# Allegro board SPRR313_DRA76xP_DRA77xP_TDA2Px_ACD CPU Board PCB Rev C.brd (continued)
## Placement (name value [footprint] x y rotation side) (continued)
TP82  TP  [TP-30RD13]  123.44 46.35 0 top
TP83  SMT-TP  [TP1-70X135]  4.7 14.99 0 top
TP84  SMT-TP  [TP1-70X135]  197.74 14.1 0 top
TP85  TP  [TP1-6040]  190.75 37.47 0 top
TP86  SMT-TP  [TP1-70X135]  212.98 165.23 180 bottom
TP87  SMT-TP  [TP1-70X135]  8.89 175.13 180 bottom
TP88  TP  [TP1-18RD8]  128.52 83.69 0 top
TP89  TP  [TP20]  44.96 50.04 270 bottom
TP90  TP  [TP-30RD13]  142.49 32.13 0 top
TP91  TP  [TP1-6040]  19 87.04 180 bottom
TP92  SMT-TP  [TP1-70X135]  4.95 15.11 90 bottom
TP93  SMT-TP  [TP1-70X135]  197.74 14.48 180 bottom
TP94  TP  [TP-30RD13]  47.75 128.78 0 top
TP95  TP  [TP-30RD13]  47.75 130.18 0 top
TP96  TP  [TP-30RD13]  211.46 123.95 0 top
TP97  TP  [TP1-18RD8]  64.01 74.04 0 top
TP98  TP  [TP-30RD13]  205.23 123.95 0 top
TP99  SMT-TP  [TP1-70X135]  107.06 123.32 0 top
TP100  SMT-TP  [TP1-70X135]  101.22 85.6 180 bottom
U1  TPS2065D  [SO8-25X75]  18.67 174.24 180 top
U2  TPS2065D  [SO8-25X75]  29.84 162.81 270 top
U3  FT232RQ  [QFN32_5X5]  167.51 164.59 90 top
U4  74LV1G126CRG4  [DCK-5]  55.12 163.7 90 top
U5  TPS3808G09DBVRG4  [DBV6-27X39-6]  60.45 161.29 270 top
U6  TPS3808G09DBVRG4  [DBV6-27X39-6]  60.45 157.48 270 top
U7  74LVC1G08DCK  [DCK-5]  55.12 157.35 90 top
U8  DS90UB921-Q1  [RHS48-11X34]  152.15 155.32 90 top
U9  LM74610  [DGK8-14X70]  177.8 154.05 180 top
U10  CDCM9102RHBR  [QFN32_202SQ]  25.15 149.1 90 top
U11  CDCE813QPWRQ1  [PW14-12X70]  159.38 146.3 0 top
U12  MT29F4G16ABADAWP:D  [TSOP48-10X60-MICRON]  131.95 143.51 270 top
U13  tps1h100-q1  [PWP14-14X70-PAD]  8.89 140.72 270 top
U14  tps1h100-q1  [PWP14-14X70-PAD]  211.84 147.19 180 top
U15  MTFC8GLWDM-3M AIT Z  [FBGA153-169-P5-COMBO]  150.5 132.21 0 top
U16  74LVC1G08DCK  [DCK-5]  210.69 129.03 0 top
U17  SN74LVC1G04DCK  [DCK-5]  129.16 114.81 0 top
U18  TPS43351QDAPRQ1  [DAP38]  175.26 113.03 270 top
U19  TPD12S016RKTR  [RKT24]  13.97 111.76 0 top
U20  S25FL256SAGMFV001  [SO16-25X75-300]  108.71 110.24 90 top
U21  PCF8575  [PW24-14X70]  200.41 77.98 270 top
U22  tpd1e05u06  [DPY-RDPADS]  14.1 106.68 135 top
U23  SN74LVC1G04DCK  [DCK-5]  68.83 105.03 0 top
U24  tpd1e05u06  [DPY-RDPADS]  14.1 104.9 225 top
U25  tpd1e05u06  [DPY-RDPADS]  16 103.63 135 top
U26  tpd1e05u06  [DPY-RDPADS]  16 101.85 225 top
U27  SN74LVC1G04DCK  [DCK-5]  119.63 101.6 0 top
U28  tpd1e05u06  [DPY-RDPADS]  16 99.57 135 top
U29  tpd1e05u06  [DPY-RDPADS]  16 97.79 225 top
U30  PCF8575  [PW24-14X70]  200.66 66.42 270 top
U31  tpd1e05u06  [DPY-RDPADS]  14.1 96.52 135 top
U32  tpd1e05u06  [DPY-RDPADS]  14.1 94.74 225 top
U33  tpd1e05u06  [DPY-RDPADS]  11.81 80.64 135 top
U34  tpd1e05u06  [DPY-RDPADS]  11.81 79.12 225 top
U35  tpd1e05u06  [DPY-RDPADS]  11.81 77.47 135 top
U36  tpd1e05u06  [DPY-RDPADS]  11.81 75.95 225 top
U37  TPS73101DBVR  [DBV5-27X39]  121.92 42.04 0 top
U38  O917A14ATRGZRQ1  [RGZ48-11X34]  163.7 69.98 90 top
U39  SN74AVC8T245RHL  [RHL24-PVQFN-TI]  17.02 67.56 90 top
U40  LP87565CRNFRQ1  [VQFNHR26]  137.54 60.07 0 top
U41  SN74AVC4T245RGYR  [RGY16-12X34]  17.02 59.56 90 top
U42  X577PXGACD  [SKTBGA-ZKK-6334-P784]  92.58 56.36 270 top
U43  SN74AVC8T245RHL  [RHL24-PVQFN-TI]  17.02 51.94 90 top
U44  SN74LVC1G04DCK  [DCK-5]  157.86 57.28 270 top
U45  TPS77018DBVT  [DBV5-27X39]  184.78 48.9 180 top
U46  74LVC1G08DCK  [DCK-5]  196.22 44.96 0 top
U47  74LVC1G08DCK  [DCK-5]  199.39 44.96 0 top
U48  74LVC1G08DCK  [DCK-5]  203.84 44.96 0 top
U50  TLV320AIC3106  [RGZ48-11X34]  175.13 43.31 270 top
U51  74LV1G126CRG4  [DCK-5]  116.2 41.78 270 top
U52  TPD4E002  [DRL5-12X40]  214.12 41.15 180 top
U53  TMP102AIDRLT  [DRL6-12X30]  110.13 40.77 180 top
U54  74LV1G126CRG4  [DCK-5]  116.2 38.86 270 top
U55  PCA9306/PCA9306-Q1  [DCU8-10X50]  17.14 37.08 180 top
U56  TPS74801  [DRC10-11X33]  3.43 28.07 0 top
U57  TCAN1042HGVQ1  [SO8-25X75]  199.77 30.73 270 top
U58  TCAN1042HGVQ1  [SO8-25X75]  213.74 25.02 180 top
U59  MT41K512M16HA-125 AIT:A (IT)  [BGA6X16-P8-RE-PKG]  64.77 23.98 0 top
U60  MT41K512M16HA-125 AIT:A (IT)  [BGA6X16-P8-RE-PKG]  77.47 23.98 0 top
U61  MT41K512M8RH-125-AAT:E  (IT)  [INTBGA6X13-P8-RA-PKG]  113.92 23.37 0 top
U62  MT41K512M8RH-125-AAT:E  (IT)  [INTBGA6X13-P8-RA-PKG]  128.27 23.37 0 top
U63  MT41K512M8RH-125-AAT:E (IT)  [BGA6X13-P8-RA-PKG]  90.17 22.78 0 top
U65  INA226AIDGSR  [DGS10-11X60]  154.43 86.11 0 bottom
U66  INA226AIDGSR  [DGS10-11X60]  159.13 86.11 0 bottom
U67  INA226AIDGSR  [DGS10-11X60]  178.56 61.85 270 bottom
U68  INA226AIDGSR  [DGS10-11X60]  179.83 65.53 270 bottom
U69  INA226AIDGSR  [DGS10-11X60]  179.83 69.22 270 bottom
U70  INA226AIDGSR  [DGS10-11X60]  162.69 58.04 0 bottom
U71  INA226AIDGSR  [DGS10-11X60]  179.83 54.48 90 bottom
U72  INA226AIDGSR  [DGS10-11X60]  172.97 57.78 180 bottom
U73  INA226AIDGSR  [DGS10-11X60]  179.83 58.17 270 bottom
U74  INA226AIDGSR  [DGS10-11X60]  172.34 83.95 0 bottom
U75  INA226AIDGSR  [DGS10-11X60]  182.88 77.09 270 bottom
U76  INA226AIDGSR  [DGS10-11X60]  150.37 59.18 90 bottom
U77  INA226AIDGSR  [DGS10-11X60]  146.94 63.25 270 bottom
U78  INA226AIDGSR  [DGS10-11X60]  146.94 55.24 270 bottom
U79  INA226AIDGSR  [DGS10-11X60]  130.3 40.64 270 top
U80  INA226AIDGSR  [DGS10-11X60]  141.22 14.22 270 top
U81  INA226AIDGSR  [DGS10-11X60]  145.8 92.33 0 top
U82  INA226AIDGSR  [DGS10-11X60]  163.83 86.23 0 bottom
U83  INA226AIDGSR  [DGS10-11X60]  176.91 84.07 0 bottom
U84  INA226AIDGSR  [DGS10-11X60]  146.94 67.18 90 bottom
U85  INA226AIDGSR  [DGS10-11X60]  137.54 73.41 0 bottom
U86  INA226AIDGSR  [DGS10-11X60]  137.54 46.86 180 bottom
U87  INA226AIDGSR  [DGS10-11X60]  150.37 92.33 0 top
U88  INA226AIDGSR  [DGS10-11X60]  166.62 98.3 270 bottom
U89  INA226AIDGSR  [DGS10-11X60]  179.96 93.85 90 bottom
U90  INA226AIDGSR  [DGS10-11X60]  187.07 145.8 0 bottom
U91  INA226AIDGSR  [DGS10-11X60]  182.88 73.28 270 bottom
U92  TPD4S014DSQ  [DSQ10-SON]  73.53 174.24 0 bottom
U93  TPS74801  [DRC10-11X33]  82.8 164.08 0 bottom
U94  SN74LVC1G04DCK  [DCK-5]  48.13 163.32 0 bottom
U95  SN74LVC1G04DCK  [DCK-5]  43.05 163.32 0 bottom
U96  TPS22965DSG  [DSG8-11X20]  121.41 157.1 180 bottom
U97  TPD2E001DRL-Q1  [DRL5-12X40]  139.06 156.72 0 bottom
U98  TPD2E001DRL-Q1  [DRL5-12X40]  134.49 156.72 0 bottom
U99  TPD2E001DRL-Q1  [DRL5-12X40]  129.92 156.72 0 bottom
U100  TPD2E001DRL-Q1  [DRL5-12X40]  126.11 156.72 0 bottom
U101  DP83867IRPAP  [PAP64-12X70]  91.95 151.64 0 bottom
U102  TPS74801  [DRC10-11X33]  77.98 149.48 0 bottom
U103  74LVC1G08DCK  [DCK-5]  82.55 143.89 270 bottom
U104  S29GL512S10TFI010  [TSOP56-12X75]  131.95 143.51 90 bottom
U105  SN74LVC1G125DCKR  [DCK-5]  64.77 143.51 180 bottom
U106  74LVC1G08DCK  [DCK-5]  82.55 141.1 270 bottom
U107  74LVC1G08DCK  [DCK-5]  82.55 138.05 270 bottom
U108  DP83867IRPAP  [PAP64-12X70]  98.3 131.32 0 bottom
U109  SN74LVC1G125DCKR  [DCK-5]  142.24 128.78 0 bottom
U110  PCF8575  [PW24-14X70]  73.28 128.02 270 bottom
U111  SN74LVC1G125DCKR  [DCK-5]  62.61 127.13 90 bottom
U112  SN74LVC1G125DCKR  [DCK-5]  62.48 131.57 90 bottom
U113  SN74LVC2G74DCT  [DCT8-14X70]  216.15 133.35 0 bottom
U114  TPS3808G33DBVRG4  [DBV6-27X39-6]  210.57 133.48 0 bottom
U115  DS90Ux949AQ  [RGC64-11X28]  27.94 122.94 90 bottom
U116  SN74LVC1G04DCK  [DCK-5]  146.94 117.47 270 bottom
U117  TPS74801  [DRC10-11X33]  30.99 102.36 180 bottom
U118  SN74LVC1G04DCK  [DCK-5]  79.12 105.16 90 bottom
U119  TPS22965DSG  [DSG8-11X20]  147.83 99.82 0 bottom
U120  TPD4S014DSQ  [DSQ10-SON]  5.71 89.41 0 bottom
U121  SN74LVC1G04DCK  [DCK-5]  148.21 82.42 180 bottom
U122  tps2115a  [DRB8-14X33-PAD]  111.76 78.23 0 bottom
U123  NP  [OSC4-71X79]  14.1 18.41 90 top
U124  TXS0108EPW  [PW20-14X70]  14.22 23.37 270 bottom
U125  CDCEL925  [PW16-14X70]  49.53 51.31 180 bottom
U126  TPS3808G09DBVRG4  [DBV6-27X39-6]  206.12 51.82 180 bottom
U127  TPS3808G09DBVRG4  [DBV6-27X39-6]  196.85 51.69 180 bottom
U128  TXS0108EPW  [PW20-14X70]  7.49 50.04 180 bottom
U129  74CBTLV1G125CRG4  [DCK-5]  215.14 45.47 0 bottom
U130  74CBTLV1G125CRG4  [DCK-5]  211.2 45.47 0 bottom
U131  74CBTLV1G125CRG4  [DCK-5]  215.14 40.89 0 bottom
U132  SN74LVC1T45  [DCK-17X60-6]  8 38.48 90 bottom
U133  74CBTLV1G125CRG4  [DCK-5]  215.14 36.96 0 bottom
U134  NP-TPS22965DSG  [DSG8-11X20]  136.4 38.73 270 bottom
U135  PCA9306/PCA9306-Q1  [DCU8-10X50]  25.53 40.51 180 bottom
U136  MT41K512M8RH-125-AAT:E  (IT)  [BGA6X13-P8-RA-PKG]  128.27 23.37 180 bottom
U137  MT41K512M8RH-125-AAT:E  (IT)  [BGA6X13-P8-RA-PKG]  113.92 23.37 180 bottom
U138  TPS54116QRTWTQ1  [RGE24-11X28-4MM]  148.59 24.26 0 bottom
U139  24WC256  [SO8-25X75-295]  28.19 54.61 0 bottom
U140  tps2115a  [DRB8-14X33-PAD]  19.56 30.99 0 top
U141  TUSB4020BI-Q1  [PHP48-12X70]  51.56 121.28 270 top
U142  74CBTLV1G125CRG4  [DCK-5]  166.88 157.35 180 bottom
U143  74CBTLV1G125CRG4  [DCK-5]  163.96 157.35 180 bottom
U144  SN74LVC1G04DCK  [DCK-5]  127.89 106.17 180 top
U145  SN74LVC1G04DCK  [DCK-5]  124.97 106.17 180 top
U146  PCA9306/PCA9306-Q1  [DCU8-10X50]  34.92 54.61 180 top
U147  NP-TPS3803-01-Q1  [DCK-5]  200.28 127 0 top
U148  TLV7103318-Q1  [DSE6]  188.47 65.41 0 top
Y1  25.0000MHz  [XTAL4-32X35-ABM10]  18.41 147.96 270 top
Y2  TC32M5I32K7680  [XTAL4-35X28]  14.73 30.99 90 top
Y3  NP-25MHz  [XTAL2-75X94]  102.74 154.81 90 bottom
Y4  NP-25MHz  [XTAL2-75X94]  109.09 134.49 90 bottom
Y5  NP-20MHz  [XTAL2-75X94]  66.55 55.98 270 bottom
Y6  25MHz-8pF  [XTAL4-32X35-ABM10]  53.85 51.31 270 bottom
Y7  NP-22.5792MHz  [XTAL4-55X87]  61.21 49 0 bottom
Y8  24 MHz/18pF  [XTAL2-75X94]  53.98 130.43 180 bottom
ZJ1  TP  [MHP125-250]  30.53 175.13 0 top
ZJ2  MNTHOLE  [MHP125-250]  190.37 175.13 0 top
ZJ3  MNTHOLE  [MHP125-250]  190.37 45.29 0 top
ZJ4  MNTHOLE  [MHP125-250]  34.8 44.32 0 top

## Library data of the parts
C1 C135 C166 C177 C341 C365 C515 C520 C564 = CAP NP: User Part Number: USERPART#; Tolerance: TOLERANCE
C2 C3 C125 C254 C255 C657 C662 C665 C670 = CAP: User Part Number: X; Tolerance: X
C4 C9 C15 C16 = CAP NP: Tolerance: TOLERANCE; User Part Number: USERPART#; room: uart
C5 = CAP NP: User Part Number: USERPART#; Tolerance: TOLERANCE; room: USB
C6 C8 C29 C40 C45 C57-C60 C118 C124 C275 C298 C346 C610 C626 = CAP NP: Tolerance: X; User Part Number: X
C7 C11 C13 C14 C17 C18 C21 C30 C32 C33 C35-C37 C51 C61 C77 C79-C81 C89 C102 C128 C129 C131 C136 C273 C278 C303 C306-C309 C314 C315 C317 C324 C325 C327 C330 C333 C334 C336 C708 C709 C711 = CAP: Tolerance: X; User Part Number: X
C10 = CAP NP_2: Tolerance: X; User Part Number: X; room: uart
C12 C56 C120 C121 C216 C226-C252 C265 C266 C279 C291 C305 C313 C316 C323 C329 C331 C335 C337 C340 C342 C353-C355 C379 C380 C429 C430 C470 C525 C532 C543 C547 C555 C687 C688 C705-C707 C710 = CAP NP: Tolerance: TOLERANCE; User Part Number: USERPART#
C19 C20 = CAP: User Part Number: USERPART#; Tolerance: TOLERANCE; signal model: CAP_C402-25_0.1UF_0.1uF
C22 = Cap 100nF Cermc 16V 10% 603_4: Tolerance: TOLERANCE; User Part Number: USERPART#; room: micro sd
C23-C25 C31 C38 C39 C42 C50 C54 C63-C65 C68 C70 C73-C76 C78 C83 C87 C88 C90-C101 C103-C108 C110-C116 C122 C137 C138 C257 C258 C260 C261 C292-C297 C312 C326 C328 C332 C338 C339 C343-C345 C348-C352 C361 C362 C523 C524 C545 C577 C609 C623 C691-C704 = CAP: Tolerance: TOLERANCE; User Part Number: USERPART#
C26-C28 C256 C267 C304 C310 = Cap 100nF Cermc 16V 10% 603_4: Tolerance: TOLERANCE; User Part Number: USERPART#
C34 C41 C48 C287 = CAP NP_0: Tolerance: X; User Part Number: X; room: serdes clock
C43 C44 = CAP .1 uF 10% 0603: Tolerance: X; User Part Number: X; signal model: CAP_.1_UF_10%_0603_C603_C43_C44; room: pcie
C46 C290 = CAP .1 uF 10% 0603: Tolerance: TOLERANCE; User Part Number: USERPART#
C47 C603 = CAP NP_0: Tolerance: X; User Part Number: X
C49 = CAP NP_2: Tolerance: TOLERANCE; User Part Number: USERPART#; room: NAND FLASH
C52 C53 = CAP .1 uF 10% 0603: User Part Number: X; Tolerance: X; signal model: CAP_.1_UF_10%_0603_C603-35X45_0_0.1uF; room: tms320
C55 C281-C283 C285 C286 C288 = CAP NP_0: Tolerance: TOLERANCE; User Part Number: USERPART#; room: serdes clock
C62 C300 C301 C550 C579 = CAP NP: User Part Number: X; Tolerance: X
C66 C67 C69 = CAPACITOR NON-POL: Tolerance: TOLERANCE; User Part Number: USERPART#; room: NAND FLASH
C71 C142 C144 C280 C356 C713 = CAP NP_2: Tolerance: TOLERANCE; User Part Number: USERPART#
C72 = CAP_POL: Tolerance: X; User Part Number: X
C82 C84 C130 C132-C134 = CAP .1 uF 10% 0603: Tolerance: TOLERANCE; User Part Number: USERPART#; signal model: CAP__1_UF_10__0603_C402_25__1UF__1uF
C85 C86 C150-C152 C200 = CAP_AM_0402_0.1uf_x7r_16v_10_2: Tolerance: TOLERANCE; User Part Number: USERPART#
C109 C117 C119 C126 C127 = C_0: Tolerance: X; User Part Number: X
C123 = CAP NP: Tolerance: TOLERANCE; User Part Number: USERPART#; room: SPI FLASH
C139 C180 C195 C270 C271 C277 C320 C360 C366 C415 C416 C419 C453 C454 C471 C514 C529 C546 C549 C576 C593 C624 = CAP: User Part Number: USERPART#; Tolerance: TOLERANCE
C140 C141 C145 C147 C155 C162 C163 C172-C174 C197 = CAP_AM_0805_10uf_x7r_10v_10_2
C143 C146 C148 C158 C160 C650-C652 = CAP_AM_1210_47uf_x7r_6.3v_20_X: User Part Number: X; Tolerance: X
C149 = CAP_AM_0805_4.7uf_x7r_10v_10_2
C153 C154 C169 C170 = CAP_0805_22uF_X7R_6.3V_20%_X_SD: Tolerance: 20%; User Part Number: X; tolerance: 20%
C156 C157 C161 C167 C168 C563 C575 C580 C636 = CAP_AM_0805_10uf_x7r_10v_10_X: Tolerance: X; User Part Number: X
C159 = CAP_AM_0603_1.0uf_x7r_16v_10_X: Tolerance: X; User Part Number: X
C164 C165 = CAP_AM_0603_2.2uf_x7r_6.3v_10_X: Tolerance: X; User Part Number: X
C171 C185 C191 C594 C638 = CAPACITOR POL_0: User Part Number: X; Tolerance: X; room: aic3106
C175 C176 C179 C183 C184 C190 C192 C206 C530 C540-C542 C544 C548 C639 = CAP NP: User Part Number: USERPART#; Tolerance: TOLERANCE; room: aic3106
C178 = CAP NP_2: User Part Number: X; Tolerance: X; room: aic3106
C181 C182 C186 C187 C210 C421 C426 = CAP_AM_0402_0.47uf_x7s_10v_20_2: Tolerance: TOLERANCE; User Part Number: USERPART#
C188 C381 C522 = CAP NP_1: Tolerance: TOLERANCE; User Part Number: USERPART#
C189 C369 C372-C374 C382-C384 C411 C428 C439 C440 C455 C456 C484 C485 C497 C503-C505 C516 C551 = CAP_AM_0508_1uF_X7S_4V_20_2
C193 = CAP_AM_0805_10uf_x7r_10v_10_2: Tolerance: X; User Part Number: X
C194 C196 C198 C199 C201 C207 C557 C561 C562 C568 C570 C589 C590 C607 C608 C615 C627 C628 C641 C664 C666-C669 C671-C678 C680-C683 C686 = CAP NP_0: User Part Number: USERPART#; Tolerance: TOLERANCE
C202 C209 C213 C224 C225 C387 C391 C396 C425 C433 C435 C438 C441 C446-C448 C452 C459 C462 C466 C482 C487 C489 C491 C492 C495 C498 C499 C501 C506 C509 C512 C513 C533-C539 C559 C566 C572 C574 C581 C582 C584-C586 C591 C596-C600 C604 C612 C613 C616-C618 C620 C622 C629 C631-C633 C637 C645 C647 C653 C654 = CAP_AM_0402_0.47uf_x7s_10v_20_2
C203 C635 = CAP: Tolerance: X; User Part Number: X; room: aic3106
C204 C205 C221 C606 C643 = CAP NP_0: User Part Number: USERPART#; Tolerance: TOLERANCE; room: ddr bank1 caps
C208 C212 C222 C556 C567 C569 C602 C605 C611 C614 C625 C640 C642 C644 C648 C649 C656 C658-C661 C663 C679 C684 C685 = CAP NP_0: User Part Number: USERPART#; Tolerance: TOLERANCE; room: ddr bank0 caps
C211 C214 C215 C408 C413 C601 = C_10uF/6.3V_X5R_0603: Tolerance: TOLERANCE; User Part Number: USERPART#
C217 C219 C363 C368 C371 C389 C392-C395 C397-C401 C422 C424 C427 C431 C432 C434 C436 C444 C445 C460 C461 C463 C464 C472 C476 C483 C493 C502 C508 C511 C519 C553 C554 C558 C560 C565 C571 C573 C583 C588 C592 C595 C619 C621 C630 C634 C655 = CAP_AM_0402_0.1uf_x7r_16v_10_2
C218 C220 C223 = CAP_AM_0603_10uf_x7s_6v3_20_2
C259 C274 = CAP NP_1: Tolerance: TOLERANCE; User Part Number: USERPART#; room: pcie
C262-C264 C272 C276 = CAP NP_2: Tolerance: TOLERANCE; User Part Number: USERPART#; room: pcie
C268 C284 C299 C311 = CAP NP_3: Tolerance: X; User Part Number: X
C269 C289 C347 = Cap 100nF Cermc 16V 10% 603_3: Tolerance: TOLERANCE; User Part Number: USERPART#
C302 = Cap 100nF Cermc 16V 10% 603_4: Tolerance: TOLERANCE; User Part Number: USERPART#; room: PATA MUX
C318 C319 C321 C322 = CAP: Tolerance: TOLERANCE; User Part Number: USERPART#; signal model: CAP_C402-25_100NF_100nF
C357 = CAP NP: User Part Number: USERPART#; Tolerance: TOLERANCE; room: I2C EXPANDER
C358 = CAP_AM_0402_220pf_C0G_50v_5_2: Tolerance: TOLERANCE; User Part Number: USERPART#
C359 = CAP NP: Tolerance: TOLERANCE; User Part Number: USERPART#; room: PATA MUX
C364 C367 C370 C378 C386 C388 C437 C442 C443 C449-C451 C465 C469 C473 C475 C477 C478 C481 C486 C494 C496 C500 C510 C521 C526 = CAP_AM_0402_1uF_X7S_10V_10_2
C375 C390 C402 C409 C420 = C_4.7uF/0402/6.3V_X5R_0402: Tolerance: X; User Part Number: X
C376 C377 C385 C403 C404 C406 C407 C410 C412 C414 C423 = C_2.2uF/0402/6.3V_X5R_0402: Tolerance: X; User Part Number: X
C405 C458 = CAP_AM_0402_0.1uf_x7r_16v_10%_X: Tolerance: TOLERANCE; User Part Number: USERPART#
C417 C418 = C_10uF/6.3V_X5R_0603: Tolerance: X; User Part Number: X
C457 C474 C517 C518 = CAP_AM_0402_18pf_C0G_50v_5_2
C467 C468 C488 C490 = CAP NP_2: User Part Number: USERPART#; Tolerance: TOLERANCE
C479 C480 C689 C690 C712 = CAP NP_3: Tolerance: TOLERANCE; User Part Number: USERPART#
C507 = C_0: User Part Number: USERPART#; Tolerance: TOLERANCE; room: aic3106
C531 C646 = CAP .1 uF 10% 0603: User Part Number: USERPART#; Tolerance: TOLERANCE
C552 = Cap 100nF Cermc 16V 10% 603_3: User Part Number: USERPART#; Tolerance: TOLERANCE
C578 = SC10N16V2KX_0: User Part Number: USERPART#; Tolerance: TOLERANCE; room: ddr bank0 caps
C587 = Cap 100nF Cermc 16V 10% 603_4: Tolerance: X; User Part Number: X
D1 = DIODE_0: User Part Number: USERPART#; Tolerance: TOLERANCE
D2 D3 = Diode_SMCJ15CA
D24 = DIODE ZENER: Tolerance: TOLERANCE; User Part Number: USERPART#
DS1 DS6 = LED_RED_0: Tolerance: X; User Part Number: X
DS2 = LED_RED_0: User Part Number: X; Tolerance: X; room: I2C EXPANDER
DS3-DS5 = LED_0: User Part Number: X; Tolerance: X; room: I2C EXPANDER
E1 E11 = NFM_1: Tolerance: TOL; User Part Number: PART#
E2-E10 E12 = FIL_AM_3T0805_0.47uF_10V_0.3A_2
EXP_P1 EXP_P3 = J - SamTec QSH020 40pin_2
EXP_P2 = J - SamTec QSH060 120pin_2: User Part Number: PART#; Tolerance: TOL
F1 = NANO-SMF_0: User Part Number: X; Tolerance: X
FL1 = DLW21SN121HQ2: Tolerance: TOL; User Part Number: PART#; signal model: DLW21SN121HQ2_EMI_36X15_DLW21_D_DLW21SN121HQ2
FL2-FL6 = DLW21SN900HQ2: User Part Number: PART#; Tolerance: TOL; signal model: DLW21SN900HQ2_EMI_36X15_DLW21_D_DLW21SN900HQ2
FL7-FL9 = DLW21SN121HQ2: User Part Number: PART#; Tolerance: TOL
FL10 FL11 = DLW21SN121HQ2: User Part Number: PART#; Tolerance: TOL; signal model: DLW21SN121HQ2_EMI_36X15_DLW21_D_DLW21SN121HQ2
J1 J4-J7 = HEADER 2: Tolerance: X; User Part Number: X
J2 = PWR_JACK_0
J3 = USBMINI_B_0: room: uart
J8 = HEADER 36: room: USB
J9 J10 = HEADER 3: User Part Number: X; Tolerance: X
J11 = 99S20D-40MA5-Y-HSD-2
J12 = HEADER 7_0: Tolerance: X; User Part Number: X
J13 = MIPI-QTH-030_1: User Part Number: PART#; Tolerance: TOL
J14 = HEADER 5: User Part Number: X; Tolerance: X
J15 = HEADER 36
J16 = CON2: User Part Number: X; Tolerance: X
J17 = HEADER 40_0
J18 = CONN_AXT340124_40PINS_SMT_X: User Part Number: PART#; Tolerance: TOL
J19 = QSH-030: User Part Number: PART#; Tolerance: TOL
J20 J21 = HEADER 5X2: Tolerance: X; User Part Number: X
JP1 JP2 = HEADER 2: User Part Number: X; Tolerance: X
L1 = INDUCTOR_3: User Part Number: X; Tolerance: X
L2 = FERRITE CHIP_0: Tolerance: X; User Part Number: X; room: uart
L3 = INDUCTOR_3: User Part Number: X; Tolerance: X; room: USB
L4-L6 L8 L9 L19 L25-L29 L32 L33 = FERRITE CHIP_0: Tolerance: X; User Part Number: X
L7 = FERRITE CHIP_0: Tolerance: X; User Part Number: X; room: serdes clock
L10 = INDUCTOR
L11 = INDUCTOR: Tolerance: TOLERANCE; User Part Number: USERPART#
L12-L14 L17 L18 = IND_1.47uH_DFE252012C_R47N: Tolerance: TOLERANCE; User Part Number: USERPART#
L15 L16 L20 L21 L31 = IND_1008_0.47uH_6A_20%_X_SD: Tolerance: +/-20%; User Part Number: X; tolerance: +/-20%
L22-L24 = INDUCTOR: User Part Number: X; Tolerance: X; room: aic3106
L30 = INDUCTOR_0: Tolerance: X; User Part Number: X
MHC1-MHC4 TP2 TP12 TP14 TP16-TP19 TP22 TP26 TP58 TP60 TP63 TP64 TP69-TP74 TP76-TP82 TP85 TP90 TP91 TP94-TP96 TP98 = TESTPOINT
P1 = D4S20D-40ML5-Y
P2 = USB-A connector: User Part Number: PART#; Tolerance: TOL
P3 P4 = 66058414_1
P5 = QSH-020-01-L-D-DP-A: User Part Number: PART#; Tolerance: TOL
P6 = PCI Connector_0: room: pcie
P7 = HDMI-RA-19_0: Tolerance: TOL; User Part Number: PART#
P8 = AU-Y1009_3-AB-R: User Part Number: X; Tolerance: X
P9 = HEADER 50x2
P10-P13 = Kycon ST-3500_0: room: aic3106
P14 = molex-502774-0891: User Part Number: X; Tolerance: X
P15 = QSH-020-01-L-D-DP-A: Tolerance: TOL; User Part Number: PART#
Q1 = SUD50P04-08: User Part Number: USERPART#; Tolerance: TOLERANCE
Q2 Q7-Q10 = MOSFET_CSD16406Q3_0: User Part Number: X; Tolerance: X
Q3-Q6 Q11-Q13 = MOSFET N_1: Tolerance: X; User Part Number: X
Q16 = NX3008CBKS: User Part Number: X; Tolerance: X
Q18 Q19 = BSS138PS: User Part Number: X; Tolerance: X
R1 R10 R11 R14 R17 R22 R25 R33 R37 R38 R40 R41 R43 R44 R49 R64 R69 R86 R99 R100 R103-R106 R108 R109 R111 R112 R129 R134 R139 R157 R158 R163 R165-R168 R188 R217 R222 R223 R226 R227 R229 R230 R232 R242 R253 R257 R259 R266 R269 R273 R278 R309 R327 R329 R338 R348 R351 R353 R356 R357 R359 R360 R366-R368 R373-R376 R379 R380 R382 R383 R390-R394 R396 R397 R399 R403 R407 R409 R421 R424 R430-R433 R452 R458 R460 R461 R463 R468 R471 R474 R475 R478 R482-R484 R487 R489 R491 R493 R494 R498 R501 R535 R550-R552 R569 R572 R573 R576 R579 R581 R584 R585 R587-R592 R594 R618-R623 R626 R634-R636 R641 R648 R649 R654 R666 R670 R678-R680 R682 R687 R694 R695 R702 R704 R705 R712 R729 R730 R735-R737 R745-R748 = R: Tolerance: TOLERANCE; User Part Number: USERPART#
R2 R149 R154 R155 R159 R341 R384-R389 R395 R398 R401 R402 R414 R415 R417 R420 R441 R445 R446 R476 R479 R480 R488 R496 R711 R714 R716 = RESISTOR: User Part Number: USERPART#; Tolerance: TOLERANCE
R3 R15 R20 R53 R140 R142 R324 R361 R473 = R_3: User Part Number: X; Tolerance: X
R7 = R_0: User Part Number: USERPART#; Tolerance: TOLERANCE; room: uart
R8 = R: Tolerance: TOLERANCE; User Part Number: USERPART#; room: usb
R9 R330-R335 = RESISTOR: User Part Number: USERPART#; Tolerance: TOLERANCE; room: micro sd
R12 R317 = RESISTOR: User Part Number: USERPART#; Tolerance: TOLERANCE; room: pcie
R13 R18 R319 = R_2: User Part Number: USERPART#; Tolerance: TOLERANCE; room: pcie
R16 R19 R57 R369 R370 R372 R381 R404 = R: User Part Number: USERPART#; Tolerance: TOLERANCE; room: pcie
R21 R31 R39 R289 R290 R342 R500 = R: User Part Number: X; Tolerance: X
R23 R36 R59 R61 R63 R67 R95 R96 R297 R350 R719 R722 R724-R728 R731 R732 R756 = R_2: User Part Number: USERPART#; Tolerance: TOLERANCE
R24 R91 R143 R164 R176-R178 R193 R233 R234 R243 R244 R247 R270 R316 R457 R465 R511 R515 R520 R525 R527 R571 R615 = R: Tolerance: TOLERANCE; User Part Number: USERPART#; signal model: R_R201-6P6SPC_0_0
R26-R29 R48 R340 R349 = R: User Part Number: USERPART#; Tolerance: TOLERANCE; room: serdes clock
R30 R34 R42 R66 R93 R94 R137 R147 R150 R153 R161 R169 R172 R174 R180 R184 R186 R190 R248 R250 R263 R264 R267 R276 R277 R280-R282 R284 R285 R292 R296 R305-R308 R310 R311 R318 R322 R323 R325 R326 R328 R336 R337 R354 R358 R362-R365 R371 R377 R378 R400 R405 R406 R408 R411-R413 R416 R419 R422 R425-R429 R443 R444 R449 R450 R466 R467 R470 R472 R492 R497 R512 R516 R518 R519 R521-R523 R528 R534 R538 R540 R541 R547 R597 R602 R613 R616 R625 R640 R643 R647 R651 R652 R658 R664 R665 R667 R672 R673 R689 R698 R699 R709 R717 R733 R734 R742-R744 R753 = R: User Part Number: USERPART#; Tolerance: TOLERANCE
R32 R160 R162 R179 R182 R183 R189 R191 R192 R196 R204 R208 R219 R220 R249 R642 R671 R703 = RES_0508_0.01_1%_1W_X: Tolerance: X; User Part Number: X
R35 R52 = R: User Part Number: USERPART#; Tolerance: TOLERANCE; room: NAND FLASH
R45 R51 R58 R630 R677 R681 R683 R749-R752 = R_1: Tolerance: TOLERANCE; User Part Number: USERPART#
R46 R50 R62 R68 R595 R608 R609 = R_2: Tolerance: TOLERANCE; User Part Number: USERPART#
R47 R60 R97 R435-R440 R455 R459 R462 R464 R469 R477 R481 R485 R490 R495 = R_1: User Part Number: USERPART#; Tolerance: TOLERANCE
R54 R55 R352 = R: User Part Number: USERPART#; Tolerance: TOLERANCE; signal model: R_R402_25_22_22
R56 R355 = R_1: User Part Number: USERPART#; Tolerance: TOLERANCE; signal model: R_1_R402_25_22_22
R65 R98 = R_2: User Part Number: X; Tolerance: X
R70-R85 R113-R128 = R_1: Tolerance: TOLERANCE; User Part Number: USERPART#; room: boot switches
R87 R88 R148 R156 = RESISTOR: User Part Number: X; Tolerance: X
R89 R90 R131 R133 R135 R144 R151 R170 R171 R173 R175 R181 R185 R187 R536 R542 R543 = R: User Part Number: USERPART#; Tolerance: TOLERANCE; signal model: R_R402_25_0_0
R92 R101 R102 R110 R132 R312-R315 R320 R321 R410 R423 R442 R447 R448 R451 R453 R454 R456 R600 R601 = RESISTOR: Tolerance: TOLERANCE; User Part Number: USERPART#
R107 R486 R656 R657 R713 = R_0: User Part Number: USERPART#; Tolerance: TOLERANCE
R130 R136 R152 = RESISTOR: User Part Number: USERPART#; Tolerance: TOLERANCE; room: SPI FLASH
R138 R141 = RESISTOR
R145 R146 = R: User Part Number: USERPART#; Tolerance: TOLERANCE; signal model: R_R402_25_10_10
R194 R205 R225 R533 R537 R548 R549 R575 = RES_0603_0.02_1%_2.2A_0.1W_X: User Part Number: X; Tolerance: X
R195 R197-R203 R207 R210 R212 R265 R272 R553 R555 R557 R559-R568 R570 R574 R577 = R: User Part Number: USERPART#; Tolerance: TOLERANCE; signal model: R_R201-6P6SPC_22_22
R206 R209 R213 R214 R216 R218 R221 R224 R228 R231 R235 R245 R252 R255 R268 R271 R434 R554 R556 R558 R578 R580 R582 R583 R586 R596 R603 R607 R624 R655 = R: User Part Number: USERPART#; Tolerance: TOLERANCE; signal model: R_R201-6P6SPC_0_0
R211 = R: Tolerance: TOLERANCE; User Part Number: USERPART#; room: tms320
R215 R283 R286 R291 R546 R688 R692 R706 R710 = R_10K_0402_1%_Multi: User Part Number: USERPART#; Tolerance: TOLERANCE
R236 R246 R251 R254 R256 R279 R604-R606 R610 R612 R614 R617 R628 R632 R633 R645 R697 R700 R701 = R_0: Tolerance: TOLERANCE; User Part Number: USERPART#; room: aic3106
R237-R240 = R_0: Tolerance: TOLERANCE; User Part Number: USERPART#; signal model: R_0_R402-25_10_10; room: aic3106
R241 = RESISTOR: Tolerance: TOLERANCE; User Part Number: USERPART#; room: aic3106
R274 R662 = R_3: Tolerance: X; User Part Number: X
R275 R696 = R: Tolerance: TOLERANCE; User Part Number: USERPART#; room: aic3106
R287 R288 R653 = R: Tolerance: X; User Part Number: X
R298 = R: Tolerance: TOLERANCE; User Part Number: USERPART#; room: USB
R299-R302 = RES_0: Tolerance: TOLERANCE; User Part Number: USERPART#
R339 R343-R347 = RESISTOR: User Part Number: USERPART#; Tolerance: TOLERANCE; signal model: RESISTOR_R402-25_33_33
R418 = RESISTOR: User Part Number: USERPART#; Tolerance: TOLERANCE; signal model: RESISTOR_R402_25_0_0
R499 R502 R503 R505 R506 R508 R509 = R: Tolerance: TOLERANCE; User Part Number: USERPART#; room: I2C EXPANDER
R504 R507 R510 R517 = R_0: Tolerance: TOLERANCE; User Part Number: USERPART#; room: I2C EXPANDER
R513 R514 = RESISTOR: Tolerance: X; User Part Number: X; signal model: RESISTOR_R0508_0.01_0.01
R524 R526 R529-R532 = R0402-22: Tolerance: TOLERANCE; User Part Number: USERPART#; signal model: R0402_22_R201_6P6SPC_22_22
R539 = R: Tolerance: TOLERANCE; User Part Number: USERPART#; signal model: R_R402_25_0_0
R544 R545 = R_10K_0402_1%_Multi: Tolerance: TOLERANCE; User Part Number: USERPART#
R593 R598 R599 R611 R637 R638 R659 R663 = R: Tolerance: TOLERANCE; User Part Number: USERPART#; room: jtag
R639 R644 R646 R650 R668 R669 = RESISTOR_0: Tolerance: TOLERANCE; User Part Number: USERPART#
R674 R676 = 1KR2F_0: Tolerance: TOLERANCE; User Part Number: USERPART#; room: ddr bank0 caps
R675 R684 = 1KR2F
R685 R686 R693 = R
R690 R691 = R_0
R707 R708 R754 R755 = RES_0402_10k_1.0%_0.063W_X: User Part Number: USERPART#; Tolerance: 1.0%; tolerance: 1.0%
R738-R740 = RESISTOR_0: User Part Number: USERPART#; Tolerance: TOLERANCE
RJ1 RJ6-RJ10 RJ12-RJ17 = RJUMP3: Tolerance: TOLERANCE; User Part Number: USERPART#
RJ2 RJ3 RJ5 = RJUMP3B: Tolerance: TOLERANCE; User Part Number: USERPART#
RJ4 = RJUMP3: Tolerance: TOLERANCE; User Part Number: USERPART#; signal model: RJUMP3_JMP402-25_22_22
RN1 RN3 RN5 RN10 RN12 RN14 = R-Pak4_0: User Part Number: PART#; Tolerance: TOL; room: ddr bank0
RN2 RN4 RN6 RN11 RN13 RN15 = R-Pak4_0
RN7-RN9 = R-Pak4_0: Tolerance: TOL; User Part Number: PART#; signal model: R_PAK4_0_RPAK8_10X25_28V_RPACK4_RPACK4_22; room: ddr bank1
RU1 U4 = SN74LVC1G125_0: Tolerance: TOL; User Part Number: PART#; room: pcie
RU2 = SN74CBT3257PW: User Part Number: X; Tolerance: X
RU3 = SN74LVC1G125_0: Tolerance: TOL; User Part Number: PART#; room: NAND FLASH
RU4 = SN74CBT3257PW: User Part Number: X; Tolerance: X; signal model: SN74CBT3257PW_TSSOP16-14X70_ru4
RU5 = SN74CBT16212DGGR: Tolerance: X; User Part Number: X; signal model: SN74CBT16212DGGR_DGG56_12X80_SN_SN74CBTLV16212GR
RU6 = SN74LVC1G125_0: Tolerance: TOL; User Part Number: PART#; signal model: SN74LVC1G125_0_DCK-5_74CBTLV1G1_74CBTLV1G125CRG4
RU7 = SN74CBT16212DGGR: Tolerance: X; User Part Number: X; signal model: SN74CBT16212DGGR_DGG56-12X80_SN_ru7
RU8 = SN74CBT16214DGGR_1: Tolerance: X; User Part Number: X; signal model: SN74CBT16214DGGR_1_DGG56-12X80_ru8ab1ab2
RU9 = 74PCT245_3: Tolerance: X; User Part Number: X; signal model: 74PCT245_3_DBQ20-14X70_SN74CBTL_SN74CBTLV3245DBQ
RU10 RU21 = SN74CBT3257PW_0: Tolerance: X; User Part Number: X
RU11 RU12 RU24 RU25 U51 U54 U105 U109 U111 U112 U129-U131 U133 U142 U143 = SN74LVC1G125_0: Tolerance: TOL; User Part Number: PART#
RU13 RU16 = SN74CBT16212DGGR: Tolerance: X; User Part Number: X; signal model: SN74CBT16212DGGR_DGG56-12X80_a1b2
RU14 = SN74CBT3257PW: User Part Number: X; Tolerance: X; signal model: SN74CBT3257PW_TSSOP16-14X70_SN7_SN74CBTLV3257PW
RU15 = SN74CBT16214DGGR_1: Tolerance: X; User Part Number: X; signal model: SN74CBT16214DGGR_1_DGG56-12X80_ru15
RU17 = SN74CBT16212DGGR: Tolerance: X; User Part Number: X; signal model: SN74CBT16212DGGR_DGG56-12X80_SN_ru17; room: PATA MUX
RU18 = SN74CBT16212DGGR: Tolerance: X; User Part Number: X; signal model: SN74CBT16212DGGR_DGG56-12X80_SN_SN74CBTLV16212GR
RU19 RU22 = SN74CBT3257PW: Tolerance: X; User Part Number: X
RU20 = 74PCT245_3: User Part Number: X; Tolerance: X; signal model: 74PCT245_3_DBQ20-14X70_SN74CBTL_SN74CBTLV3245DBQ
RU23 = SN74CBT3257PW: Tolerance: X; User Part Number: X; signal model: SN74CBT3257PW_TSSOP16-14X70_ru23
SW1 = SW DIP-2: Tolerance: X; User Part Number: X
SW2 = SW PUSHBUTTON_3: User Part Number: X; Tolerance: X
SW3 SW4 = SW DIP-8: User Part Number: X; Tolerance: X
SW5 SW7-SW9 = SW PUSHBUTTON_3: Tolerance: X; User Part Number: X
SW6 = DIP_SWITCH_10: Tolerance: X; User Part Number: X
SW10 = SW DIP-4_0: Tolerance: X; User Part Number: X
TP1 TP3 TP83 TP84 TP86 TP87 TP92 TP93 TP99 TP100 = SMT-TP
TP2MA1-TP2MA27 = TP_VIA_MEM0_0
TP2MB1-TP2MB27 = TP_VIA_MEM1_0
TP4-TP6 TP8 TP20 TP21 TP23-TP25 TP27-TP30 TP39 TP55-TP57 TP65 TP75 TP97 ZJ1-ZJ4 = TestPoint1_0
TP7 TP13 TP54 TP59 TP61 TP62 = TESTPOINT: Tolerance: TOLERANCE; User Part Number: USERPART#
TP9 TP40-TP53 TP88 = TP_0
TP10 TP15 TP66-TP68 TP89 = TESTPOINT: User Part Number: USERPART#; Tolerance: TOLERANCE
TP11 = TP_0: room: serdes clock
TP31-TP38 = TEST POINT_0
U1 = tps2061_1: Tolerance: X; User Part Number: X; room: USB
U2 = tps2061_1: Tolerance: X; User Part Number: X; room: usb
U3 = FT232RQ_7: Tolerance: TOL; User Part Number: PART#; room: uart
U5 U6 = TPS3808G09DBVR_0: Tolerance: X; User Part Number: X; room: pcie
U7 = 1G08_0: Tolerance: TOL; User Part Number: PART#; room: pcie
U8 = DS90UB921Q
U9 = LM74610: User Part Number: X; Tolerance: X
U10 = CDCM9102RHBR_2: User Part Number: PART#; Tolerance: TOL; room: serdes clock
U11 = CDCE813-Q1: User Part Number: USERPART#; Tolerance: TOLERANCE
U12 = U-NAND-Micron 16bit Socket_0: room: NAND FLASH
U13 U14 = tps1h100-q1: Tolerance: X; User Part Number: X
U15 = MTFC16GJVEC-4M-169WFBGA
U16 U46-U48 U103 U106 U107 = 1G08_0: Tolerance: TOL; User Part Number: PART#
U17 U23 U27 U44 U116 U118 U144 U145 = SN74LVC1GU04_0: Tolerance: TOL; User Part Number: PART#
U18 = TPS43351QDAPRQ1_0
U19 = TPD12S016RKTR_QFN24_3: Tolerance: X; User Part Number: X
U20 = SPI_EEPROM_1: Tolerance: X; User Part Number: X; room: SPI FLASH
U21 = PCF8575_1: Tolerance: X; User Part Number: X
U22 U24-U26 U28 U29 U31-U36 = tpd1e05u06: Tolerance: X; User Part Number: X
U30 = PCF8575_1: Tolerance: X; User Part Number: X; room: I2C EXPANDER
U37 = TPS731: Tolerance: X; User Part Number: X
U38 = TPS65917Q1
U39 U43 = SN74AVC8T245_1: User Part Number: PART#; Tolerance: TOL
U40 = LP87565-Q1: User Part Number: PART#; Tolerance: TOL
U41 = SN74AVC4T245RGYR_0: Tolerance: X; User Part Number: X
U42 = IC_J6Plus_23mm_784BGA_ACD_v1.0
U45 = TPS76901_1: Tolerance: X; User Part Number: X; room: aic3106
U50 = TLV320AIC3106_0: room: aic3106
U52 = TPD4E002: Tolerance: TOL; User Part Number: PART#
U53 = TMP102AIDRLT: User Part Number: PART#; Tolerance: TOL
U55 U135 U146 = PCA9306
U56 U93 U102 = U-TPS78601_AJUST - 1_3.5A LDO: Tolerance: X; User Part Number: X
U57 = SN65HVDA541: User Part Number: X; Tolerance: X
U58 = SN65HVDA541: Tolerance: X; User Part Number: X
U59 U60 = DDR3_96BALL_X16_0
U61-U63 U136 U137 = EDJ1108DBSE_1
U65-U91 = INA220IDCN_2: User Part Number: PART#; Tolerance: TOL
U92 U120 = TPD4S014DSQ: Tolerance: TOL; User Part Number: PART#
U94 U95 = SN74LVC1GU04_1: Tolerance: TOL; User Part Number: PART#
U96 U119 U134 = TPS22965DSG: User Part Number: X; Tolerance: X
U97 U98 U100 = TPDE0001RSE_0: Tolerance: TOL; User Part Number: PART#
U99 = TPDE0001RSE_0: Tolerance: TOL; User Part Number: PART#; room: SPI FLASH
U101 U108 = DP83867IR
U104 = AM29LV256M_0: Tolerance: X; User Part Number: X
U110 = PCF8575_1: User Part Number: X; Tolerance: X
U113 = SN74LVC2G74DCT: Tolerance: X; User Part Number: X
U114 = TPS3808G09DBVR_0: Tolerance: X; User Part Number: X
U115 = DS90UB949Q
U117 = U-TPS78601_AJUST - 1_3.5A LDO: User Part Number: X; Tolerance: X
U121 = SN74LVC1GU04_0: User Part Number: PART#; Tolerance: TOL
U122 U140 = tps2115a: User Part Number: X; Tolerance: X
U123 = OSC4/SM_0: User Part Number: USERPART#; Tolerance: TOLERANCE
U124 = TXB0108PWR_0: Tolerance: X; User Part Number: X
U125 = CDCE925: Tolerance: X; User Part Number: X
U126 U127 = TPS3808G09DBVR_0: User Part Number: X; Tolerance: X
U128 = TXB0108PWR_0: User Part Number: X; Tolerance: X; signal model: TXB0108PWR_0_PW20-14X70_TXS0108_TXS0108EPW
U132 = TMP_1: User Part Number: PART#; Tolerance: TOL; signal model: TMP_1_DCK-17X60-6_SN74LVC1T45_SN74LVC1T45
U138 = TPS54116QRTWTQ1
U139 = 24WC256: User Part Number: X; Tolerance: X
U141 = TUSB4020BI-Q1
U147 = TPS3803-01-Q1: Tolerance: TOL; User Part Number: PART#
U148 = TLV7103318-Q1
Y1 = CRYSTAL 4-PIN_0: room: SERDES CLOCK
Y2 = OSC4/SM_0: User Part Number: X; Tolerance: X
Y3 Y4 Y8 = CRYSTAL_0
Y5 = CRY_SMD_20MHz_18pF_6x3.3_ABM7_2
Y6 = CRYSTAL 4-PIN_0
Y7 = CRY_SMD_22.579MHz_7x5_ECL_2

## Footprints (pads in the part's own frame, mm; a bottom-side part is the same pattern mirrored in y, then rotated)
6P6SPC
  rect 0.47x0.381 smd: 1(-0.343,0)
AMP-6605814
  round 1.016 hole 3.2 unplated: (-1.27,-6.35) (10.16,-6.35)
  round 1.422 hole 0.965: 1(-1.27,2.54) 2(0,0) 3(1.27,2.54) 4(2.54,0) 5(3.81,2.54) 6(5.08,0) 7(6.35,2.54) 8(7.62,0) 9(8.89,2.54) 10(10.16,0) D1(-2.337,-8.89) D2(-2.337,-10.922) D3(11.227,-8.89) D4(11.227,-10.922)
  round 2.032 hole 1.575: 11(-3.302,-3.302) 12(12.192,-3.302)
BGA6X13-P8-RA-PKG
  round 0.343 smd: A1(-3.2,4.801) A2(-2.4,4.801) A3(-1.6,4.801) A7(1.6,4.801) A8(2.4,4.801) A9(3.2,4.801) B1(-3.2,4) B2(-2.4,4) B3(-1.6,4) B7(1.6,4) B8(2.4,4) B9(3.2,4) C1(-3.2,3.2) C2(-2.4,3.2) C3(-1.6,3.2) C7(1.6,3.2) C8(2.4,3.2) C9(3.2,3.2) D1(-3.2,2.4) D2(-2.4,2.4) D3(-1.6,2.4) D7(1.6,2.4) D8(2.4,2.4) D9(3.2,2.4) E1(-3.2,1.6) E2(-2.4,1.6) E3(-1.6,1.6) E7(1.6,1.6) E8(2.4,1.6) E9(3.2,1.6) F1(-3.2,0.8) F2(-2.4,0.8) F3(-1.6,0.8) F7(1.6,0.8) F8(2.4,0.8) F9(3.2,0.8) G1(-3.2,0) G2(-2.4,0) G3(-1.6,0) G7(1.6,0) G8(2.4,0) G9(3.2,0) H1(-3.2,-0.8) H2(-2.4,-0.8) H3(-1.6,-0.8) H7(1.6,-0.8) H8(2.4,-0.8) H9(3.2,-0.8) J1(-3.2,-1.6) J2(-2.4,-1.6) J3(-1.6,-1.6) J7(1.6,-1.6) J8(2.4,-1.6) J9(3.2,-1.6) K1(-3.2,-2.4) K2(-2.4,-2.4) K3(-1.6,-2.4) K7(1.6,-2.4) K8(2.4,-2.4) K9(3.2,-2.4) L1(-3.2,-3.2) L2(-2.4,-3.2) L3(-1.6,-3.2) L7(1.6,-3.2) L8(2.4,-3.2) L9(3.2,-3.2) M1(-3.2,-4) M2(-2.4,-4) M3(-1.6,-4) M7(1.6,-4) M8(2.4,-4) M9(3.2,-4) N1(-3.2,-4.801) N2(-2.4,-4.801) N3(-1.6,-4.801) N7(1.6,-4.801) N8(2.4,-4.801) N9(3.2,-4.801)
BGA6X16-P8-RE-PKG
  round 0.351 smd: A1(-3.2,6) A2(-2.4,6) A3(-1.6,6) A7(1.6,6) A8(2.4,6) A9(3.2,6) B1(-3.2,5.2) B2(-2.4,5.2) B3(-1.6,5.2) B7(1.6,5.2) B8(2.4,5.2) B9(3.2,5.2) C1(-3.2,4.4) C2(-2.4,4.4) C3(-1.6,4.4) C7(1.6,4.4) C8(2.4,4.4) C9(3.2,4.4) D1(-3.2,3.6) D2(-2.4,3.6) D3(-1.6,3.6) D7(1.6,3.6) D8(2.4,3.6) D9(3.2,3.6) E1(-3.2,2.8) E2(-2.4,2.8) E3(-1.6,2.8) E7(1.6,2.8) E8(2.4,2.8) E9(3.2,2.8) F1(-3.2,2) F2(-2.4,2) F3(-1.6,2) F7(1.6,2) F8(2.4,2) F9(3.2,2) G1(-3.2,1.2) G2(-2.4,1.2) G3(-1.6,1.2) G7(1.6,1.2) G8(2.4,1.2) G9(3.2,1.2) H1(-3.2,0.4) H2(-2.4,0.4) H3(-1.6,0.4) H7(1.6,0.4) H8(2.4,0.4) H9(3.2,0.4) J1(-3.2,-0.4) J2(-2.4,-0.4) J3(-1.6,-0.4) J7(1.6,-0.4) J8(2.4,-0.4) J9(3.2,-0.4) K1(-3.2,-1.2) K2(-2.4,-1.2) K3(-1.6,-1.2) K7(1.6,-1.2) K8(2.4,-1.2) K9(3.2,-1.2) L1(-3.2,-2) L2(-2.4,-2) L3(-1.6,-2) L7(1.6,-2) L8(2.4,-2) L9(3.2,-2) M1(-3.2,-2.8) M2(-2.4,-2.8) M3(-1.6,-2.8) M7(1.6,-2.8) M8(2.4,-2.8) M9(3.2,-2.8) N1(-3.2,-3.6) N2(-2.4,-3.6) N3(-1.6,-3.6) N7(1.6,-3.6) N8(2.4,-3.6) N9(3.2,-3.6) P1(-3.2,-4.4) P2(-2.4,-4.4) P3(-1.6,-4.4) P7(1.6,-4.4) P8(2.4,-4.4) P9(3.2,-4.4) R1(-3.2,-5.2) R2(-2.4,-5.2) R3(-1.6,-5.2) R7(1.6,-5.2) R8(2.4,-5.2) R9(3.2,-5.2) T1(-3.2,-6) T2(-2.4,-6) T3(-1.6,-6) T7(1.6,-6) T8(2.4,-6) T9(3.2,-6)
C201-6P6SPC
  rect 0.47x0.381 smd: 1(-0.343,0) 2(0.343,0)
C402-25
  round 0.635 smd: 1(-0.508,0) 2(0.508,0)
C508-18X70
  rect 0.457x1.778 smd: 1(-0.445,0) 2(0.445,0)
C603-35X45
  oval 0.889x1.143 smd: 1(-0.762,0) 2(0.762,0)
C805-35X60
  oval 0.889x1.524 smd: 1(-0.965,0) 2(0.965,0)
C1206-40X70
  oval 1.016x1.778 smd: 1(-1.524,0) 2(1.524,0)
C1206-40X70-POL
  oval 1.016x1.778 smd: 1(-1.524,0) 2(1.524,0)
C1206-40X70P
  oval 1.016x1.778 smd: 1(-1.524,0) 2(1.524,0)
C1210-70X102
  rect 1.778x3.048 smd: 1(-1.803,0) 2(1.803,0)
C1210-C7343-DUAL
  rect 3.429x2.997 smd: 1(-2.616,0) 2(2.616,0)
C7343-84X118
  rect 2.134x2.997 smd: 1(-3.251,0) 2(3.251,0)
CHOKE-POWER-WE-HCC
  rect 2.286x3.607 smd: 1(-4.585,0) 2(4.585,0)
CON_MB261
  round 1.397 hole 0.991: 1(2,-2) 2(2,0) 3(0,0) 4(0,-2)
  round 2.21 hole 1.702: SH1(-3.5,3.5) SH2(-3.5,-5.5) SH3(5.5,-5.5) SH4(5.5,3.5)
CONN2-MSTBA
  rect 2.54x2.54 hole 1.397: 1(0,0)
  round 2.54 hole 1.397: 2(-5.08,0)
CONN36-52559-MIRROR
  rect 0.787x1.549 smd: (-9.754,1.422) (-9.754,-1.422) (9.754,1.422) (9.754,-1.422)
  rect 0.61x1.549 smd: 1(-8.757,-1.422) 2(-8.256,1.422) 3(-7.756,-1.422) 4(-7.256,1.422) 5(-6.755,-1.422) 6(-6.255,1.422) 7(-5.754,-1.422) 8(-5.254,1.422) 9(-4.754,-1.422) 10(-4.253,1.422) 11(-3.753,-1.422) 12(-3.252,1.422) 13(-2.752,-1.422) 14(-2.252,1.422) 15(-1.751,-1.422) 16(-1.251,1.422) 17(-0.751,-1.422) 18(-0.25,1.422) 19(0.25,-1.422) 20(0.751,1.422) 21(1.251,-1.422) 22(1.751,1.422) 23(2.252,-1.422) 24(2.752,1.422) 25(3.252,-1.422) 26(3.753,1.422) 27(4.253,-1.422) 28(4.754,1.422) 29(5.254,-1.422) 30(5.754,1.422) 31(6.255,-1.422) 32(6.755,1.422) 33(7.256,-1.422) 34(7.756,1.422) 35(8.256,-1.422) 36(8.757,1.422)
CONN-AXT40
  rect 0.229x0.813 smd: 1(-3.797,-1.689) 2(-3.797,1.689) 3(-3.399,-1.689) 4(-3.399,1.689) 5(-3,-1.689) 6(-3,1.689) 7(-2.598,-1.689) 8(-2.598,1.689) 9(-2.2,-1.689) 10(-2.2,1.689) 11(-1.798,-1.689) 12(-1.798,1.689) 13(-1.4,-1.689) 14(-1.4,1.689) 15(-1.001,-1.689) 16(-1.001,1.689) 17(-0.599,-1.689) 18(-0.599,1.689) 19(-0.201,-1.689) 20(-0.201,1.689) 21(0.201,-1.689) 22(0.201,1.689) 23(0.599,-1.689) 24(0.599,1.689) 25(0.998,-1.689) 26(0.998,1.689) 27(1.4,-1.689) 28(1.4,1.689) 29(1.798,-1.689) 30(1.798,1.689) 31(2.2,-1.689) 32(2.2,1.689) 33(2.598,-1.689) 34(2.598,1.689) 35(2.997,-1.689) 36(2.997,1.689) 37(3.399,-1.689) 38(3.399,1.689) 39(3.797,-1.689) 40(3.797,1.689)
  rect 0.711x1.194 smd: 41(-4.75,1.499) 42(-4.75,-1.499) 43(4.75,1.499) 44(4.75,-1.499)
CONN-RA-99S20D
  round 1.524 hole 0.889: 1(1,-1) 2(1,1) 3(-1,1) 4(-1,-1)
  round 1.651 hole 1.016: 5(7.2,-1) 6(7.2,1)
  round 2.7 hole 1.65: G1(3.75,3.85) G2(3.75,-3.85) G3(-3.75,-3.85) G4(-3.75,3.85)
DAP38
  oval 0.356x1.778 smd: 1(-5.852,-3.81) 2(-5.202,-3.81) 3(-4.551,-3.81) 4(-3.901,-3.81) 5(-3.251,-3.81) 6(-2.601,-3.81) 7(-1.95,-3.81) 8(-1.3,-3.81) 9(-0.65,-3.81) 10(0.001,-3.81) 11(0.65,-3.81) 12(1.301,-3.81) 13(1.951,-3.81) 14(2.601,-3.81) 15(3.252,-3.81) 16(3.902,-3.81) 17(4.55,-3.81) 18(5.2,-3.81) 19(5.85,-3.81) 20(5.851,3.81) 21(5.201,3.81) 22(4.551,3.81) 23(3.9,3.81) 24(3.25,3.81) 25(2.6,3.81) 26(1.95,3.81) 27(1.299,3.81) 28(0.649,3.81) 29(-0.001,3.81) 30(-0.651,3.81) 31(-1.301,3.81) 32(-1.952,3.81) 33(-2.6,3.81) 34(-3.25,3.81) 35(-3.9,3.81) 36(-4.55,3.81) 37(-5.2,3.81) 38(-5.85,3.81)
  rect 10.998x5.004 smd: 39(0,0)
DBQ20-14X70
  oval 0.356x1.778 smd: 1(-2.857,-2.718) 2(-2.223,-2.718) 3(-1.587,-2.718) 4(-0.953,-2.718) 5(-0.318,-2.718) 6(0.318,-2.718) 7(0.953,-2.718) 8(1.587,-2.718) 9(2.223,-2.718) 10(2.857,-2.718) 11(2.857,2.718) 12(2.223,2.718) 13(1.587,2.718) 14(0.953,2.718) 15(0.318,2.718) 16(-0.318,2.718) 17(-0.953,2.718) 18(-1.587,2.718) 19(-2.223,2.718) 20(-2.857,2.718)
DBV5-27X39
  rect 0.686x0.991 smd: 1(-0.95,-1.321) 2(0,-1.321) 3(0.95,-1.321) 4(0.95,1.321) 5(-0.95,1.321)
DBV6-27X39-6
  rect 0.686x0.991 smd: 1(-0.95,-1.321) 2(0,-1.321) 3(0.95,-1.321) 4(0.95,1.321) 5(0,1.321) 6(-0.95,1.321)
DCK-5
  rect 0.46x0.66 smd: 1(-0.65,-0.991) 2(0,-0.991) 3(0.65,-0.991) 4(0.65,0.991) 5(-0.65,0.991)
DCK-17X60-6
  rect 0.46x0.66 smd: 1(-0.65,-0.991) 2(0,-0.991) 3(0.65,-0.991) 4(0.65,0.991) 5(0,0.991) 6(-0.65,0.991)
DCT8-14X70
  oval 0.356x1.778 smd: 1(-0.975,-1.844) 2(-0.325,-1.844) 3(0.325,-1.844) 4(0.975,-1.844) 5(0.975,1.841) 6(0.325,1.841) 7(-0.325,1.841) 8(-0.975,1.841)
DCU8-10X50
  oval 0.254x1.27 smd: 1(-0.747,-1.499) 2(-0.249,-1.499) 3(0.249,-1.499) 4(0.747,-1.499) 5(0.747,1.499) 6(0.249,1.499) 7(-0.249,1.499) 8(-0.747,1.499)
DGG56-12X80
  oval 0.305x2.032 smd: 1(-6.749,-3.632) 2(-6.248,-3.632) 3(-5.748,-3.632) 4(-5.248,-3.632) 5(-4.75,-3.632) 6(-4.249,-3.632) 7(-3.749,-3.632) 8(-3.249,-3.632) 9(-2.748,-3.632) 10(-2.25,-3.632) 11(-1.75,-3.632) 12(-1.25,-3.632) 13(-0.749,-3.632) 14(-0.249,-3.632) 15(0.249,-3.632) 16(0.749,-3.632) 17(1.25,-3.632) 18(1.75,-3.632) 19(2.25,-3.632) 20(2.748,-3.632) 21(3.249,-3.632) 22(3.749,-3.632) 23(4.249,-3.632) 24(4.75,-3.632) 25(5.248,-3.632) 26(5.748,-3.632) 27(6.248,-3.632) 28(6.749,-3.632) 29(6.749,3.632) 30(6.248,3.632) 31(5.748,3.632) 32(5.248,3.632) 33(4.75,3.632) 34(4.249,3.632) 35(3.749,3.632) 36(3.249,3.632) 37(2.748,3.632) 38(2.25,3.632) 39(1.75,3.632) 40(1.25,3.632) 41(0.749,3.632) 42(0.249,3.632) 43(-0.249,3.632) 44(-0.749,3.632) 45(-1.25,3.632) 46(-1.75,3.632) 47(-2.25,3.632) 48(-2.748,3.632) 49(-3.249,3.632) 50(-3.749,3.632) 51(-4.249,3.632) 52(-4.75,3.632) 53(-5.248,3.632) 54(-5.748,3.632) 55(-6.248,3.632) 56(-6.749,3.632)
DGK8-14X70
  oval 0.356x1.778 smd: 1(-0.975,-2.225) 2(-0.325,-2.225) 3(0.325,-2.225) 4(0.975,-2.225) 5(0.975,2.223) 6(0.325,2.223) 7(-0.325,2.223) 8(-0.975,2.223)
DGS10-11X60
  oval 0.279x1.524 smd: 1(-1.001,-2.286) 2(-0.5,-2.286) 3(0,-2.286) 4(0.5,-2.286) 5(1.001,-2.286) 6(1.001,2.286) 7(0.5,2.286) 8(0,2.286) 9(-0.5,2.286) 10(-1.001,2.286)
DPY-RDPADS
  oval 0.61x0.508 smd: 1(-0.495,0) 2(0.495,0)
DRB8-14X33-PAD
  rect 0.356x0.851 smd: 1(-0.975,-1.473) 2(-0.325,-1.473) 3(0.325,-1.473) 4(0.975,-1.473) 5(0.975,1.473) 6(0.325,1.473) 7(-0.325,1.473) 8(-0.975,1.473)
  rect 2.388x1.6 smd: PAD(0,0)
DRC10-11X33
  rect 0.305x0.762 smd: 1(-1.001,-1.473) 2(-0.5,-1.473) 3(0,-1.473) 4(0.5,-1.473) 5(1.001,-1.473) 6(1.001,1.473) 7(0.5,1.473) 8(0,1.473) 9(-0.5,1.473) 10(-1.001,1.473)
  custom 0.406x0.406 smd: 11(0,0)
DRL5-12X40
  rect 0.305x1.016 smd: 1(-0.5,-0.813) 2(0,-0.813) 3(0.5,-0.813) 4(0.5,0.813) 5(-0.5,0.813)
DRL6-12X30
  rect 0.305x0.762 smd: 1(-0.5,-0.813) 2(0,-0.813) 3(0.5,-0.813) 4(0.5,0.813) 5(0,0.813) 6(-0.5,0.813)
DSE6
  rect 0.305x1.143 smd: 1(-0.5,-0.597)
  rect 0.305x1.016 smd: 2(0,-0.66) 3(0.5,-0.66) 4(0.5,0.66) 5(0,0.66) 6(-0.5,0.66)
DSG8-11X20
  rect 0.279x0.508 smd: 1(-0.75,-0.965) 2(-0.25,-0.965) 3(0.25,-0.965) 4(0.75,-0.965) 5(0.75,0.965) 6(0.25,0.965) 7(-0.25,0.965) 8(-0.75,0.965)
  rect 1.6x0.889 smd: 9(0,0)
DSQ10-SON
  rect 0.229x0.711 smd: 1(-0.8,-1.067) 2(-0.399,-1.067) 3(0,-1.067) 4(0.399,-1.067) 5(0.8,-1.067) 6(0.8,1.067) 7(0.399,1.067) 8(0,1.067) 9(-0.399,1.067) 10(-0.8,1.067)
  rect 1.524x0.889 smd: 11(0,0)
EMI-36X15-DLW21
  rect 0.914x0.381 smd: 1(-0.838,0.406) 2(0.838,0.406) 3(0.838,-0.406) 4(-0.838,-0.406)
EMI-36X15-DLW21-RDPADS
  oval 0.914x0.381 smd: 1(-0.838,0.406) 2(0.838,0.406) 3(0.838,-0.406) 4(-0.838,-0.406)
EMI-NFM21P
  rect 0.889x0.813 smd: 1(-1.118,0) 3(1.118,0)
  rect 0.508x2.007 smd: 2(0,0)
FBGA153-169-P5-COMBO
  round 0.254 smd: A1(-3.249,3.249) A2(-2.749,3.249) A3(-2.249,3.249) A4(-1.75,3.249) A5(-1.25,3.249) A6(-0.75,3.249) A7(-0.25,3.249) A8(0.25,3.249) A9(0.75,3.249) A10(1.25,3.249) A11(1.75,3.249) A12(2.249,3.249) A13(2.749,3.249) A14(3.249,3.249) B1(-3.249,2.749) B2(-2.749,2.749) B3(-2.249,2.749) B4(-1.75,2.749) B5(-1.25,2.749) B6(-0.75,2.749) B7(-0.25,2.749) B8(0.25,2.749) B9(0.75,2.749) B10(1.25,2.749) B11(1.75,2.749) B12(2.249,2.749) B13(2.749,2.749) B14(3.249,2.749) C1(-3.249,2.249) C2(-2.749,2.249) C3(-2.249,2.249) C4(-1.75,2.249) C5(-1.25,2.249) C6(-0.75,2.249) C7(-0.25,2.249) C8(0.25,2.249) C9(0.75,2.249) C10(1.25,2.249) C11(1.75,2.249) C12(2.249,2.249) C13(2.749,2.249) C14(3.249,2.249) D1(-3.249,1.75) D2(-2.749,1.75) D3(-2.249,1.75) D4(-1.75,1.75) D12(2.249,1.75) D13(2.749,1.75) D14(3.249,1.75) E1(-3.249,1.25) E2(-2.749,1.25) E3(-2.249,1.25) E5(-1.25,1.25) E6(-0.75,1.25) E7(-0.25,1.25) E8(0.25,1.25) E9(0.75,1.25) E10(1.25,1.25) E12(2.249,1.25) E13(2.749,1.25) E14(3.249,1.25) F1(-3.249,0.75) F2(-2.749,0.75) F3(-2.249,0.75) F5(-1.25,0.75) F10(1.25,0.75) F12(2.249,0.75) F13(2.749,0.75) F14(3.249,0.75) G1(-3.249,0.25) G2(-2.749,0.25) G3(-2.249,0.25) G5(-1.25,0.25) G10(1.25,0.25) G12(2.249,0.25) G13(2.749,0.25) G14(3.249,0.25) H1(-3.249,-0.25) H2(-2.749,-0.25) H3(-2.249,-0.25) H5(-1.25,-0.25) H10(1.25,-0.25) H12(2.249,-0.25) H13(2.749,-0.25) H14(3.249,-0.25) J1(-3.249,-0.75) J2(-2.749,-0.75) J3(-2.249,-0.75) J5(-1.25,-0.75) J10(1.25,-0.75) J12(2.249,-0.75) J13(2.749,-0.75) J14(3.249,-0.75) K1(-3.249,-1.25) K2(-2.749,-1.25) K3(-2.249,-1.25) K5(-1.25,-1.25) K6(-0.75,-1.25) K7(-0.25,-1.25) K8(0.25,-1.25) K9(0.75,-1.25) K10(1.25,-1.25) K12(2.249,-1.25) K13(2.749,-1.25) K14(3.249,-1.25) L1(-3.249,-1.75) L2(-2.749,-1.75) L3(-2.249,-1.75) L12(2.249,-1.75) L13(2.749,-1.75) L14(3.249,-1.75) M1(-3.249,-2.249) M2(-2.749,-2.249) M3(-2.249,-2.249) M4(-1.75,-2.249) M5(-1.25,-2.249) M6(-0.75,-2.249) M7(-0.25,-2.249) M8(0.25,-2.249) M9(0.75,-2.249) M10(1.25,-2.249) M11(1.75,-2.249) M12(2.249,-2.249) M13(2.749,-2.249) M14(3.249,-2.249) MA4(-1.75,6.748) MA6(-0.75,6.748) MA9(0.75,6.748) MA11(1.75,6.748) MAE1(-3.249,-5.249) MAE14(3.249,-5.249) MAG2(-2.749,-6.248) MAG13(2.749,-6.248) MAH4(-1.75,-6.748) MAH6(-0.75,-6.748) MAH9(0.75,-6.748) MAH11(1.75,-6.748) MB2(-2.749,6.248) MB13(2.749,6.248) MD1(-3.249,5.249) MD14(3.249,5.249) N1(-3.249,-2.749) N2(-2.749,-2.749) N3(-2.249,-2.749) N4(-1.75,-2.749) N5(-1.25,-2.749) N6(-0.75,-2.749) N7(-0.25,-2.749) N8(0.25,-2.749) N9(0.75,-2.749) N10(1.25,-2.749) N11(1.75,-2.749) N12(2.249,-2.749) N13(2.749,-2.749) N14(3.249,-2.749) P1(-3.249,-3.249) P2(-2.749,-3.249) P3(-2.249,-3.249) P4(-1.75,-3.249) P5(-1.25,-3.249) P6(-0.75,-3.249) P7(-0.25,-3.249) P8(0.25,-3.249) P9(0.75,-3.249) P10(1.25,-3.249) P11(1.75,-3.249) P12(2.249,-3.249) P13(2.749,-3.249) P14(3.249,-3.249)
FH12-40-SH
  rect 1.346x0.3 smd: 1(0,9.754) 2(0,9.253) 3(0,8.753) 4(0,8.252) 5(0,7.752) 6(0,7.254) 7(0,6.754) 8(0,6.253) 9(0,5.753) 10(0,5.253) 11(0,4.755) 12(0,4.255) 13(0,3.754) 14(0,3.254) 15(0,2.753) 16(0,2.256) 17(0,1.755) 18(0,1.255) 19(0,0.754) 20(0,0.254) 21(0,-0.246) 22(0,-0.747) 23(0,-1.247) 24(0,-1.748) 25(0,-2.248) 26(0,-2.748) 27(0,-3.249) 28(0,-3.749) 29(0,-4.249) 30(0,-4.75) 31(0,-5.25) 32(0,-5.751) 33(0,-6.251) 34(0,-6.751) 35(0,-7.252) 36(0,-7.752) 37(0,-8.252) 38(0,-8.753) 39(0,-9.253) 40(0,-9.754)
  rect 2.21x1.803 smd: 41(-3.251,11.659) 42(-3.251,-11.659)
FUSEFOLDER-OMNI-BLOK
  rect 4.242x3.81 smd: 1(-3.2,0) 2(3.2,0)
HDMI-SMT-W-FLANGE-RDPADS
  oval 0.279x1.905 smd: 1(4.75,0) 2(4.249,0) 3(3.749,0) 4(3.249,0) 5(2.748,0) 6(2.248,0) 7(1.748,0) 8(1.247,0) 9(0.747,0) 10(0.246,0) 11(-0.254,0) 12(-0.754,0) 13(-1.255,0) 14(-1.755,0) 15(-2.256,0) 16(-2.756,0) 17(-3.256,0) 18(-3.757,0) 19(-4.257,0)
  round 2.032 hole 1.295: MTG1(-7.239,-1.001) MTG2(7.239,-1.001) MTG3(-7.849,-5.9) MTG4(7.849,-5.9)
IND2-65X90-IHLP1616
  rect 1.651x2.286 smd: 1(-1.651,0) 2(1.651,0)
IND2-115X213-12MM
  rect 2.921x5.41 smd: 1(-4.978,0) 2(4.978,0)
IND2520-40X80
  rect 1.016x2.032 smd: 1(-1.118,0) 2(1.118,0)
INTBGA6X13-P8-RA-PKG
  round 0.343 smd: A1(-3.2,4.801) A2(-2.4,4.801) A3(-1.6,4.801) A7(1.6,4.801) A8(2.4,4.801) A9(3.2,4.801) B1(-3.2,4) B2(-2.4,4) B3(-1.6,4) B7(1.6,4) B8(2.4,4) B9(3.2,4) C1(-3.2,3.2) C2(-2.4,3.2) C3(-1.6,3.2) C7(1.6,3.2) C8(2.4,3.2) C9(3.2,3.2) D1(-3.2,2.4) D2(-2.4,2.4) D3(-1.6,2.4) D7(1.6,2.4) D8(2.4,2.4) D9(3.2,2.4) E1(-3.2,1.6) E2(-2.4,1.6) E3(-1.6,1.6) E7(1.6,1.6) E8(2.4,1.6) E9(3.2,1.6) F1(-3.2,0.8) F2(-2.4,0.8) F3(-1.6,0.8) F7(1.6,0.8) F8(2.4,0.8) F9(3.2,0.8) G1(-3.2,0) G2(-2.4,0) G3(-1.6,0) G7(1.6,0) G8(2.4,0) G9(3.2,0) H1(-3.2,-0.8) H2(-2.4,-0.8) H3(-1.6,-0.8) H7(1.6,-0.8) H8(2.4,-0.8) H9(3.2,-0.8) J1(-3.2,-1.6) J2(-2.4,-1.6) J3(-1.6,-1.6) J7(1.6,-1.6) J8(2.4,-1.6) J9(3.2,-1.6) K1(-3.2,-2.4) K2(-2.4,-2.4) K3(-1.6,-2.4) K7(1.6,-2.4) K8(2.4,-2.4) K9(3.2,-2.4) L1(-3.2,-3.2) L2(-2.4,-3.2) L3(-1.6,-3.2) L7(1.6,-3.2) L8(2.4,-3.2) L9(3.2,-3.2) M1(-3.2,-4) M2(-2.4,-4) M3(-1.6,-4) M7(1.6,-4) M8(2.4,-4) M9(3.2,-4) N1(-3.2,-4.801) N2(-2.4,-4.801) N3(-1.6,-4.801) N7(1.6,-4.801) N8(2.4,-4.801) N9(3.2,-4.801)
